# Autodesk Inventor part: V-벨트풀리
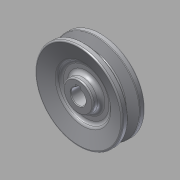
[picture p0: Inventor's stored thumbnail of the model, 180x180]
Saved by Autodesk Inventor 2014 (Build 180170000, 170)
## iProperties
Created: 2016-08
Part Number: V-벨트풀리
Material: 알루미늄 6061
Document SubType Name: Modeling
Designer: mduedu
Density: 2.71 g/cm^3
Appearance: 알루미늄 - 평지
Author: mduedu
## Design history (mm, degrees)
sketch "스케치1"
  geometry: L1 (0, 9.5)-(0, -9.5); L2 (0, 9.5)-(35, 9.5); L3 (35, 9.5)-(35, 4.825); L4 (35, 4.825)-(26, 2.074); L5 (26, 2.074)-(26, 0); L6 (0, 0)-(26, 0); L7 (0, -9.5)-(35, -9.5); L8 (35, -9.5)-(35, -4.825); L9 (35, -4.825)-(26, -2.074); L10 (26, -2.074)-(26, 0); L11 (32.3, 9.5)-(32.3, -9.5); 3 further points
  constraints: 22 end point, 6 point on line, 4 perpendicular, 3 symmetric about line, 1 coincident, 1 horizontal alignment, 1 midpoint, 1 parallel, 1 vertical
  dimensions: "d0" = 19 distance of L1.start L1.end; "d2" = 70 diameter of L8 L1; "d4" = 6.3 distance between parallel lines of L10 L11; "d5" = 2.7 distance between parallel lines of L11 L8; "d6" = 8 distance of point (32.3, -4) point (32.3, 4); "d7" = 34 deg angle of L9 L4
revolve "회전1" sketch "스케치1" stored, may be unused: angle "d8" = 90 deg
sketch "스케치2"
  geometry: L1 (-2, 0)-(2, 0); L2 (2, 0)-(2, 7.8); L3 (2, 7.8)-(-2, 7.8); L4 (-2, 7.8)-(-2, 0); C1 r 6 at (0, 0); 2 further points
  constraints: 8 end point, 2 coincident, 2 parallel, 1 centre point, 1 horizontal, 1 midpoint, 1 perpendicular
  dimensions: "d9" = 12 diameter of C1; "d11" = 4 distance of L2.end L3.end; "d12" = 7.8 distance of L1.end L2.end
extrude "돌출1" cut sketch "스케치2" stored distance "d13" = 10; taper "d14" = 0 deg
sketch "스케치3"
  geometry: L1 (35, 4.825)-(26, 2.074) reference; L2 (26, 2.074)-(26, -2.074) reference; L3 (0, 0)-(26, 0); L4 (35, 9.5)-(35, 4.825) reference; L5 (-35, 9.5)-(35, 9.5) reference; L6 (35, 9.5)-(21, 5.22); L7 (21, 5.22)-(21, 3); L8 (21, 3)-(12, 3); L9 (12, 3)-(12, 9.5); L10 (0, 9.5)-(0, -9.5); L11 (5.657, -9.5)-(-6, -9.5) reference; L12 (12, 9.5)-(35, 9.5)
  constraints: 14 end point, 3 midpoint, 2 parallel, 2 perpendicular, 2 point on line, 1 collinear, 1 horizontal
  dimensions: "d15" = 3 distance between parallel lines of L3 L8; "d17" = 42 diameter of L7 L10; "d18" = 24 diameter of L9 L10
revolve "회전2" sketch "스케치3" stored, may be unused: angle "d19" = 90 deg
fillet "모깎기1" dims "d20" = 0.5, "d21" = 1, "d22" = 1
fillet "모깎기2" dims "d23" = 3
fillet "모깎기3" dims "d24" = 3
fillet "모깎기4" dims "d25" = 3
chamfer "모따기1" distance "d26" = 0.5; stored, may be unused: second distance "d27" = 2, angle "d28" = 45 deg
fillet "모깎기5" dims "d29" = 1
node "솔리드1"
mirror "대칭1"
